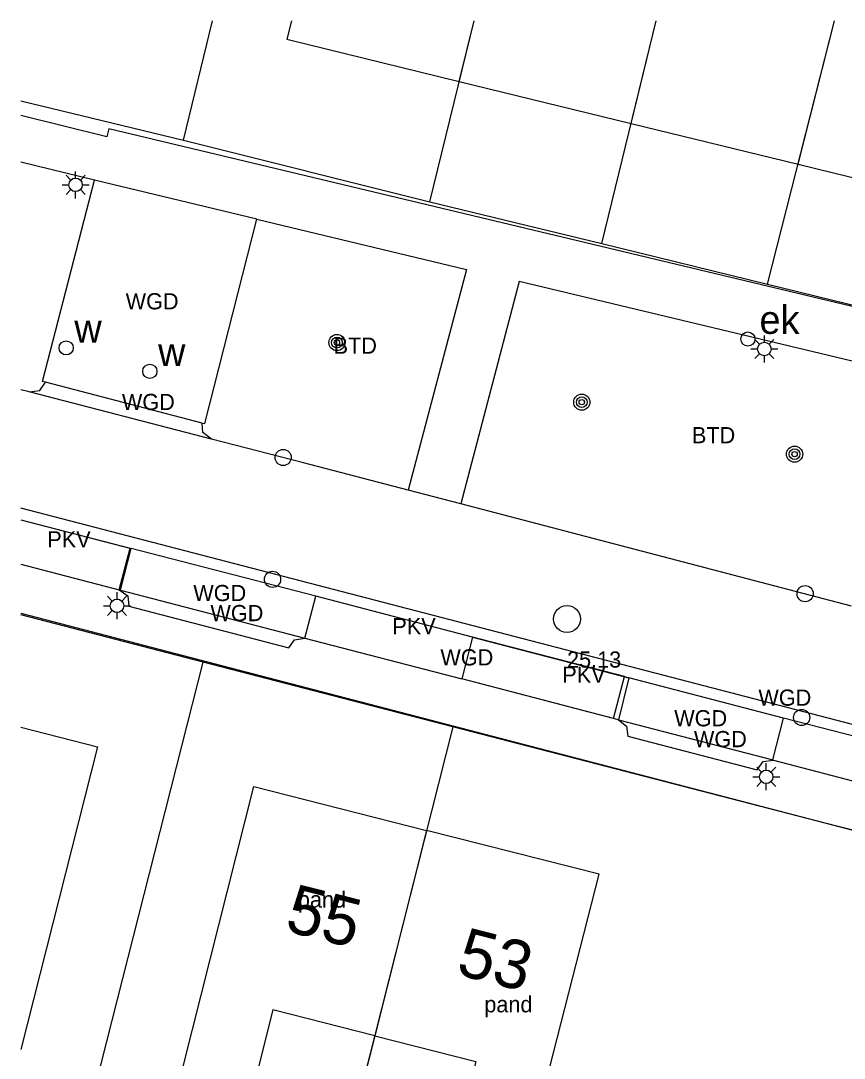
# Model space of a CAD drawing. Extents: x 198240 to 198429, y 356553 to 356721.
# Drawn here: x 198239.79 to 198270.31, y 356682.19 to 356720.63 of the extents above; entities that cross this region are included whole.
import ezdxf

# ---------------------------------------------------------------- set-up
doc = ezdxf.new("R2010")
doc.units = 0
for name, color, linetype in [('begroeid terreindeel kenmerkpunt', 7, 'Continuous'), ('BOOM', 7, 'Continuous'), ('Elektrakast', 7, 'Continuous'), ('grens individueel parkeervak', 7, 'Continuous'), ('Grens maaiveld', 7, 'Continuous'), ('grens WOZ object', 7, 'Continuous'), ('hoofdgebouw', 7, 'Continuous'), ('Hoogtepunt', 7, 'Continuous'), ('huisnummerreeks BGT', 7, 'Continuous'), ('identificerend kenmerkpunt pand', 7, 'Continuous'), ('identificerend kenmerkpunt parkeervak', 7, 'Continuous'), ('Inspectieput_rioolput', 7, 'Continuous'), ('kant verharding', 7, 'Continuous'), ('kolk', 7, 'Continuous'), ('LICHTMAST', 7, 'Continuous'), ('perceelsgrens_definitief', 7, 'Continuous'), ('tussenmuur', 7, 'Continuous'), ('waterleidingput', 7, 'Continuous'), ('wegdeel kenmerkpunt', 7, 'Continuous'), ('weginrichtingselement lijn', 7, 'Continuous')]:
    doc.layers.add(name, color=color, linetype=linetype)

msp = doc.modelspace()

# ---------------------------------------------------------------- linework, layer by layer
at = {"layer": 'BOOM'}
for centre, radius in [((198251.507, 356708.706), 0.3), ((198251.507, 356708.706), 0.2), ((198251.507, 356708.706), 0.1), ((198260.58, 356706.497), 0.3), ((198260.58, 356706.497), 0.2), ((198260.58, 356706.497), 0.1), ((198268.467, 356704.57), 0.3), ((198268.467, 356704.57), 0.2), ((198268.467, 356704.57), 0.1)]:
    msp.add_circle(centre, radius, dxfattribs=at)
at = {"layer": 'Elektrakast'}
msp.add_circle((198266.737, 356708.835), 0.263, dxfattribs=at)
msp.add_circle((198266.737, 356708.835), 0.263, dxfattribs=at)
at = {"layer": 'grens individueel parkeervak'}
for p, q in [((198239.787, 356702.143), (198243.883, 356701.081)), ((198243.485, 356699.537), (198243.883, 356701.081)), ((198250.322, 356697.756), (198250.721, 356699.308)), ((198256.532, 356697.795), (198256.129, 356696.244)), ((198256.532, 356697.795), (198262.33, 356696.286)), ((198261.935, 356694.731), (198256.129, 356696.244)), ((198262.33, 356696.286), (198261.935, 356694.731)), ((198267.655, 356693.241), (198268.06, 356694.794))]:
    msp.add_line(p, q, dxfattribs=at)
at = {"layer": 'Grens maaiveld'}
for p, q in [((198248.543, 356713.283), (198242.525, 356714.717)), ((198239.787, 356702.143), (198243.839, 356701.092)), ((198243.437, 356699.55), (198243.839, 356701.092)), ((198243.839, 356701.092), (198243.883, 356701.081)), ((198262.159, 356696.331), (198256.532, 356697.795)), ((198261.754, 356694.778), (198256.129, 356696.244)), ((198261.754, 356694.778), (198262.159, 356696.331)), ((198262.159, 356696.331), (198262.33, 356696.286)), ((198261.935, 356694.731), (198261.754, 356694.778))]:
    msp.add_line(p, q, dxfattribs=at)
msp.add_lwpolyline([(198296.898, 356686.347), (198296.977, 356686.555), (198294.265, 356687.594), (198292.374, 356688.291), (198290.5, 356688.957), (198288.618, 356689.597), (198286.63, 356690.219), (198284.719, 356690.8), (198282.78, 356691.357), (198280.86, 356691.889), (198278.876, 356692.409), (198239.787, 356702.57)], dxfattribs=at)
at = {"layer": 'grens WOZ object'}
msp.add_line((198252.91, 356683.019), (198251.898, 356679.037), dxfattribs=at)
at = {"layer": 'hoofdgebouw'}
for p, q in [((198256.04, 356718.382), (198262.41, 356716.823)), ((198262.41, 356716.823), (198268.598, 356715.31))]:
    msp.add_line(p, q, dxfattribs=at)
for points in [[(198249.823, 356720.628), (198249.653, 356719.944), (198256.04, 356718.382)], [(198268.598, 356715.31), (198274.994, 356713.745), (198276.678, 356720.628)], [(198239.787, 356694.452), (198242.629, 356693.732), (198239.787, 356682.516)], [(198252.91, 356683.019), (198249.136, 356683.978), (198248.124, 356679.996), (198245.498, 356680.66), (198248.431, 356692.255), (198254.831, 356690.63)], [(198255.645, 356678.084), (198258.264, 356677.418), (198261.225, 356689.006), (198254.831, 356690.63)], [(198252.91, 356683.019), (198256.657, 356682.067), (198255.645, 356678.084)]]:
    msp.add_lwpolyline(points, dxfattribs=at)
at = {"layer": 'Inspectieput_rioolput'}
msp.add_circle((198260.034, 356698.462), 0.5, dxfattribs=at)
at = {"layer": 'kant verharding'}
for p, q in [((198246.506, 356705.721), (198240.703, 356707.237)), ((198246.855, 356705.121), (198240.1, 356706.876)), ((198256.096, 356702.725), (198254.149, 356703.234)), ((198270.578, 356698.941), (198256.096, 356702.725)), ((198250.721, 356699.308), (198243.883, 356701.081)), ((198239.787, 356700.5), (198243.437, 356699.55)), ((198243.437, 356699.55), (198243.485, 356699.537)), ((198243.485, 356699.537), (198250.322, 356697.756)), ((198256.532, 356697.795), (198250.721, 356699.308)), ((198250.322, 356697.756), (198256.129, 356696.244)), ((198268.06, 356694.794), (198262.33, 356696.286)), ((198261.935, 356694.731), (198267.655, 356693.241)), ((198273.74, 356693.315), (198268.06, 356694.794)), ((198267.655, 356693.241), (198267.689, 356693.232)), ((198267.689, 356693.232), (198273.335, 356691.761))]:
    msp.add_line(p, q, dxfattribs=at)
for points in [[(198276.227, 356708.377), (198273.833, 356708.949), (198273.906, 356709.256), (198243.052, 356716.618), (198242.98, 356716.333), (198239.787, 356717.12)], [(198242.525, 356714.717), (198239.787, 356715.391)], [(198240.703, 356707.237), (198240.599, 356707.263), (198242.525, 356714.717)], [(198246.506, 356705.721), (198246.609, 356705.705), (198248.543, 356713.283)], [(198248.543, 356713.283), (198256.306, 356711.408), (198254.149, 356703.234)], [(198273.184, 356707.397), (198258.258, 356710.969), (198256.096, 356702.725)], [(198240.1, 356706.876), (198239.787, 356706.956)], [(198240.1, 356706.876), (198240.493, 356706.931), (198240.703, 356707.237)], [(198246.855, 356705.121), (198246.533, 356705.375), (198246.506, 356705.721)], [(198254.149, 356703.234), (198250.261, 356704.25), (198246.855, 356705.121)], [(198243.437, 356699.55), (198243.76, 356699.32), (198243.79, 356698.939), (198249.724, 356697.396), (198249.932, 356697.689), (198250.322, 356697.756)], [(198239.787, 356698.674), (198277.877, 356688.756), (198279.573, 356688.328), (198281.722, 356687.74), (198283.655, 356687.172), (198285.635, 356686.576), (198287.401, 356686.002), (198289.29, 356685.363), (198291.23, 356684.694), (198293.016, 356684.031), (198294.971, 356683.265), (198298.672, 356681.879)], [(198261.935, 356694.731), (198262.243, 356694.487), (198262.285, 356694.119), (198267.084, 356692.87), (198267.305, 356693.183), (198267.689, 356693.232)]]:
    msp.add_lwpolyline(points, dxfattribs=at)
at = {"layer": 'kolk'}
for centre in [(198249.513, 356704.448), (198249.12, 356699.933), (198268.857, 356699.401), (198268.73, 356694.814)]:
    msp.add_circle(centre, 0.3, dxfattribs=at)
at = {"layer": 'LICHTMAST'}
for p, q in [((198241.82, 356714.798), (198241.82, 356715.048)), ((198241.643, 356714.725), (198241.466, 356714.902)), ((198241.997, 356714.725), (198242.174, 356714.902)), ((198241.32, 356714.548), (198241.57, 356714.548)), ((198241.466, 356714.194), (198241.643, 356714.371)), ((198241.82, 356714.048), (198241.82, 356714.298)), ((198242.174, 356714.194), (198241.997, 356714.371)), ((198242.07, 356714.548), (198242.32, 356714.548)), ((198267.346, 356708.718), (198267.346, 356708.968)), ((198267.169, 356708.645), (198266.992, 356708.822)), ((198267.523, 356708.645), (198267.7, 356708.822)), ((198266.846, 356708.468), (198267.096, 356708.468)), ((198266.992, 356708.114), (198267.169, 356708.291)), ((198267.346, 356707.968), (198267.346, 356708.218)), ((198267.7, 356708.114), (198267.523, 356708.291)), ((198267.596, 356708.468), (198267.846, 356708.468)), ((198243.179, 356699.129), (198243.002, 356699.306)), ((198243.356, 356699.202), (198243.356, 356699.452)), ((198243.533, 356699.129), (198243.71, 356699.306)), ((198242.856, 356698.952), (198243.106, 356698.952)), ((198243.606, 356698.952), (198243.856, 356698.952)), ((198243.002, 356698.598), (198243.179, 356698.775)), ((198243.356, 356698.452), (198243.356, 356698.702)), ((198243.71, 356698.598), (198243.533, 356698.775)), ((198267.416, 356692.866), (198267.416, 356693.116)), ((198267.239, 356692.793), (198267.062, 356692.97)), ((198267.593, 356692.793), (198267.77, 356692.97)), ((198266.916, 356692.616), (198267.166, 356692.616)), ((198267.062, 356692.262), (198267.239, 356692.439)), ((198267.416, 356692.116), (198267.416, 356692.366)), ((198267.77, 356692.262), (198267.593, 356692.439)), ((198267.666, 356692.616), (198267.916, 356692.616))]:
    msp.add_line(p, q, dxfattribs=at)
for centre in [(198241.82, 356714.548), (198267.346, 356708.468), (198243.356, 356698.952), (198267.416, 356692.616)]:
    msp.add_circle(centre, 0.25, dxfattribs=at)
at = {"layer": 'perceelsgrens_definitief'}
for points in [[(198245.816, 356716.204), (198246.898, 356720.628)], [(198254.955, 356713.92), (198256.586, 356720.628)], [(198261.325, 356712.377), (198263.339, 356720.628)], [(198267.469, 356710.864), (198269.949, 356720.628)], [(198239.787, 356717.665), (198245.816, 356716.204)], [(198245.816, 356716.204), (198254.955, 356713.92)], [(198254.955, 356713.92), (198261.325, 356712.377)], [(198261.325, 356712.377), (198267.469, 356710.864)], [(198267.469, 356710.864), (198276.34, 356708.694)], [(198246.545, 356696.869), (198239.787, 356698.618)], [(198239.787, 356670.263), (198246.545, 356696.869)], [(198255.802, 356694.474), (198246.545, 356696.869)], [(198255.802, 356694.474), (198252.904, 356682.997)], [(198270.038, 356690.79), (198255.802, 356694.474)], [(198298.205, 356681.89), (198294.757, 356683.22), (198291.286, 356684.488), (198287.793, 356685.695), (198284.279, 356686.84), (198280.746, 356687.922), (198277.194, 356688.941), (198273.624, 356689.897), (198270.038, 356690.79)], [(198252.904, 356682.997), (198252.378, 356680.96)]]:
    msp.add_lwpolyline(points, dxfattribs=at)
at = {"layer": 'tussenmuur'}
for p, q in [((198256.04, 356718.382), (198256.586, 356720.628)), ((198262.41, 356716.823), (198263.339, 356720.628)), ((198268.598, 356715.31), (198269.948, 356720.628)), ((198254.831, 356690.63), (198252.91, 356683.019))]:
    msp.add_line(p, q, dxfattribs=at)
at = {"layer": 'waterleidingput'}
for centre in [(198241.47, 356708.508), (198241.47, 356708.508), (198244.573, 356707.64), (198244.573, 356707.64)]:
    msp.add_circle(centre, 0.263, dxfattribs=at)
at = {"layer": 'weginrichtingselement lijn'}
msp.add_lwpolyline([(198296.898, 356686.347), (198296.977, 356686.555), (198294.265, 356687.594), (198292.374, 356688.291), (198290.5, 356688.957), (198288.618, 356689.597), (198286.63, 356690.219), (198284.719, 356690.8), (198282.78, 356691.357), (198280.86, 356691.889), (198278.876, 356692.409), (198239.787, 356702.57)], dxfattribs=at)

# ---------------------------------------------------------------- texts
at = {"layer": 'begroeid terreindeel kenmerkpunt'}
for p in [(198251.384, 356708.292), (198264.663, 356704.974)]:
    msp.add_text('BTD', height=0.6, dxfattribs=at).set_placement(p)
at = {"layer": 'Elektrakast'}
msp.add_text('ek', height=1.05, dxfattribs=at).set_placement((198267.166, 356709.026))
at = {"layer": 'Hoogtepunt'}
msp.add_text('25.13', height=0.6, dxfattribs=at).set_placement((198260.034, 356696.662))
msp.add_text('25.13', height=0.6, dxfattribs=at).set_placement((198260.034, 356696.662))
at = {"layer": 'huisnummerreeks BGT'}
for s, rotation, p in [('55', 345.8, (198249.523, 356686.921)), ('53', 345.7, (198255.872, 356685.311))]:
    msp.add_text(s, height=1.8, rotation=rotation, dxfattribs=at).set_placement(p)
at = {"layer": 'identificerend kenmerkpunt pand'}
for p in [(198250.058, 356687.77), (198256.968, 356683.89)]:
    msp.add_text('pand', height=0.6, dxfattribs=at).set_placement(p)
at = {"layer": 'identificerend kenmerkpunt parkeervak'}
for p in [(198240.773, 356701.114), (198253.56, 356697.896), (198259.859, 356696.102)]:
    msp.add_text('PKV', height=0.6, dxfattribs=at).set_placement(p)
at = {"layer": 'waterleidingput'}
for p in [(198241.774, 356708.706), (198244.877, 356707.838)]:
    msp.add_text('w', height=1.05, dxfattribs=at).set_placement(p)
at = {"layer": 'wegdeel kenmerkpunt'}
for p in [(198243.676, 356709.935), (198243.536, 356706.204), (198246.183, 356699.126), (198246.818, 356698.383), (198255.34, 356696.743), (198267.126, 356695.25), (198264.007, 356694.486), (198264.736, 356693.714)]:
    msp.add_text('WGD', height=0.6, dxfattribs=at).set_placement(p)

doc.saveas('drawing.dxf')
